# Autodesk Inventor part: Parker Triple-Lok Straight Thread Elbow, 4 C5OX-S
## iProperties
Shininess: 64.0
Length Units: 11272
Angle Units: 11279
Time Units: 11290
Mass Units: 11286
Length Display Precision: 3
Angle Display Precision: 2
Created: 2001-12
Part Number: Parker Triple-Lok Straight Thread Elbow, 4 C5OX-S
Description: Parker Triple-Lok Straight Thread Elbow, 4 C5OX-S
Document SubType Name: Modeling
Designer: Administrator
Density: 0.0
Volumn: 0.0
Area: 0.0
PropertySet Name: Model Information
Control State: 0
Master: False
Checked Out: False
Last Check In By: Charles Bliss
Last Check In Date: 2003-09-27
Author: Administrator
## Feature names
1. Extrusion1
2. Extrusion2
3. Revolution1
4. Revolution2
5. Fillet1
6. Revolution3
7. Extrusion3
8. Revolution4
9. Mirror1
10. Extrusion4
11. Extrusion5
12. Chamfer1
13. Revolution7
14. Hole1
15. Hole2
